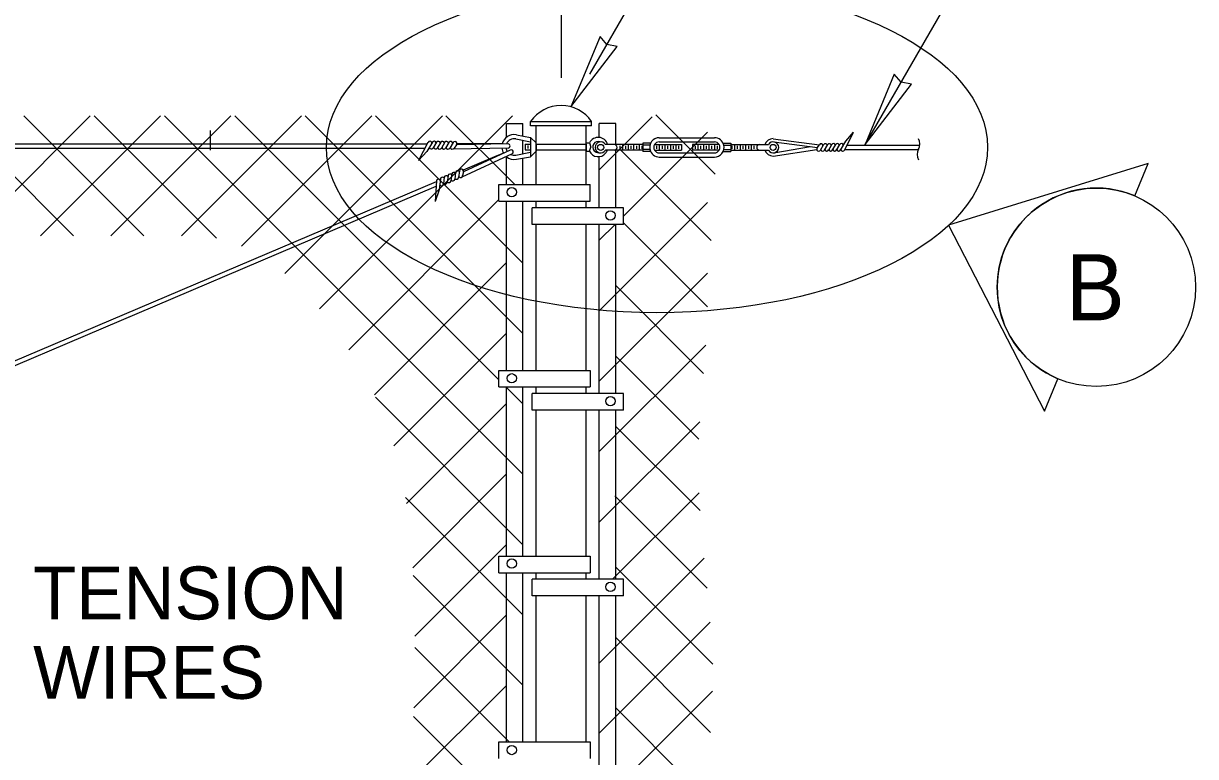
# Model space of a CAD drawing. Extents: x 99862 to 104211, y 98939 to 105076.
# Drawn here: x 102562.7 to 102917.2, y 101407.9 to 101629.6 of the extents above; entities that cross this region are included whole.
import ezdxf

# ---------------------------------------------------------------- set-up
doc = ezdxf.new("R2010")
doc.units = 0
for name, color, linetype in [('Level 11', 7, 'Continuous'), ('Level 15', 7, 'Continuous'), ('Level 2', 7, 'Continuous'), ('Level 20', 7, 'Continuous'), ('Level 4', 7, 'Continuous'), ('Level 7', 7, 'Continuous'), ('Level 9', 7, 'Continuous')]:
    doc.layers.add(name, color=color, linetype=linetype)

msp = doc.modelspace()

# ---------------------------------------------------------------- linework, layer by layer
at = {"layer": 'Level 11'}
msp.add_ellipse((102754.33, 101592.13), major_axis=(100, 0), ratio=0.5, dxfattribs=at)
at = {"layer": 'Level 15'}
for p, q in [((102725.47, 101613.16), (102725.47, 101829.45)), ((102734.02, 101614.25), (102778.38, 101691.09)), ((102817.16, 101592.77), (102846.22, 101643.09))]:
    msp.add_line(p, q, dxfattribs=at)
for points in [[(102728.32, 101604.37), (102742.32, 101622.65), (102739.2, 101623.22), (102737.15, 101625.63)], [(102728.32, 101604.37), (102742.32, 101622.65), (102739.2, 101623.22), (102737.15, 101625.63)], [(102817.27, 101592.95), (102831.27, 101611.23), (102828.15, 101611.8), (102826.1, 101614.21)], [(102817.27, 101592.95), (102831.27, 101611.23), (102828.15, 101611.8), (102826.1, 101614.21)]]:
    msp.add_lwpolyline(points, close=True, dxfattribs=at)
at = {"layer": 'Level 2'}
for p, q in [((102685.07, 101593.64), (102682.21, 101588.12)), ((102686.42, 101593.7), (102684.72, 101590.85)), ((102687.69, 101593.71), (102686.62, 101591.95)), ((102688.95, 101593.71), (102687.81, 101591.85)), ((102690.18, 101593.68), (102689.12, 101591.91)), ((102691.42, 101593.64), (102690.37, 101591.88)), ((102711.62, 101594.68), (102716.12, 101593.8)), ((102711.8, 101595.91), (102716.12, 101595.14)), ((102716.12, 101595.14), (102717.81, 101593.46)), ((102716.12, 101595.14), (102716.12, 101589.3)), ((102755.03, 101595.04), (102771.69, 101595.04)), ((102755.03, 101593.79), (102771.69, 101593.79)), ((102789.45, 101594.74), (102803.44, 101592.88)), ((102789.67, 101593.77), (102802.89, 101592.09)), ((102809.81, 101591.26), (102811.41, 101594.04)), ((102811.11, 101591.34), (102813.78, 101596.74)), ((102811.41, 101594.04), (102813.78, 101596.74)), ((102053.12, 101593.18), (102684.84, 101593.18)), ((102053.82, 101591.88), (102684.16, 101591.88)), ((102684.72, 101590.85), (102682.21, 101588.12)), ((102692.65, 101593.61), (102691.64, 101591.89)), ((102709.29, 101591.91), (102692.56, 101591.59)), ((102693.65, 101592.85), (102692.96, 101591.91)), ((102709.28, 101593.16), (102693.65, 101592.86)), ((102704.03, 101593.22), (102693.8, 101593.33)), ((102710.51, 101590.17), (102695.29, 101583.12)), ((102709.97, 101591.3), (102695.78, 101584.72)), ((102707.52, 101593.18), (102704.03, 101593.22)), ((102707.86, 101590.4), (102705.14, 101589.23)), ((102711.62, 101589.77), (102716.12, 101590.65)), ((102714.47, 101593.06), (102714.47, 101591.39)), ((102714.47, 101593.06), (102716.12, 101593.06)), ((102714.47, 101591.39), (102716.12, 101591.39)), ((102715.31, 101592.64), (102715.31, 101591.81)), ((102716.12, 101589.3), (102717.81, 101590.99)), ((102717.79, 101593.06), (102732.94, 101593.06)), ((102717.81, 101593.06), (102717.81, 101591.39)), ((102717.81, 101592.22), (102717.81, 101591.39)), ((102717.81, 101591.39), (102732.86, 101591.39)), ((102732.86, 101593.06), (102732.86, 101591.39)), ((102733.92, 101593.47), (102734.31, 101592.22)), ((102733.92, 101590.97), (102734.31, 101592.22)), ((102742.29, 101592.95), (102738.74, 101592.95)), ((102742.29, 101591.29), (102738.74, 101591.29)), ((102750.03, 101592.95), (102742.28, 101592.95)), ((102750.03, 101591.29), (102742.28, 101591.29)), ((102743.11, 101592.54), (102743.11, 101591.7)), ((102743.94, 101592.95), (102743.94, 101591.29)), ((102744.77, 101592.54), (102744.77, 101591.7)), ((102745.61, 101592.95), (102745.61, 101591.29)), ((102746.44, 101592.54), (102746.44, 101591.7)), ((102747.27, 101592.95), (102747.27, 101591.29)), ((102748.11, 101592.54), (102748.11, 101591.7)), ((102748.94, 101592.95), (102748.94, 101591.29)), ((102749.77, 101592.54), (102749.77, 101591.7)), ((102750.03, 101593.37), (102750.03, 101590.87)), ((102752.4, 101593.37), (102750.03, 101593.37)), ((102752.4, 101590.87), (102750.03, 101590.87)), ((102753.6, 101592.95), (102761.7, 101592.95)), ((102753.6, 101591.29), (102761.7, 101591.29)), ((102754.2, 101592.54), (102754.2, 101591.7)), ((102755.03, 101592.95), (102755.03, 101591.29)), ((102755.03, 101590.45), (102771.71, 101590.45)), ((102755.87, 101592.54), (102755.87, 101591.7)), ((102756.7, 101592.95), (102756.7, 101591.29)), ((102757.53, 101592.54), (102757.53, 101591.7)), ((102758.37, 101592.95), (102758.37, 101591.29)), ((102759.2, 101592.54), (102759.2, 101591.7)), ((102760.03, 101592.95), (102760.03, 101591.29)), ((102760.87, 101592.54), (102760.87, 101591.7)), ((102761.7, 101592.95), (102761.7, 101591.29)), ((102765.03, 101592.95), (102765.03, 101591.29)), ((102773.14, 101592.95), (102765.03, 101592.95)), ((102773.14, 101591.29), (102765.03, 101591.29)), ((102765.87, 101592.54), (102765.87, 101591.7)), ((102766.7, 101592.95), (102766.7, 101591.29)), ((102767.53, 101592.54), (102767.53, 101591.7)), ((102768.36, 101592.95), (102768.36, 101591.29)), ((102769.2, 101592.54), (102769.2, 101591.7)), ((102770.03, 101592.95), (102770.03, 101591.29)), ((102770.86, 101592.54), (102770.86, 101591.7)), ((102771.7, 101592.95), (102771.7, 101591.29)), ((102772.53, 101592.54), (102772.53, 101591.7)), ((102774.33, 101593.37), (102776.69, 101593.37)), ((102774.33, 101590.87), (102776.69, 101590.87)), ((102776.69, 101593.37), (102776.69, 101590.87)), ((102776.69, 101592.95), (102784.46, 101592.95)), ((102776.69, 101591.29), (102784.46, 101591.29)), ((102776.96, 101592.54), (102776.96, 101591.7)), ((102777.79, 101592.95), (102777.79, 101591.29)), ((102778.62, 101592.54), (102778.62, 101591.7)), ((102779.46, 101592.95), (102779.46, 101591.29)), ((102780.29, 101592.54), (102780.29, 101591.7)), ((102781.12, 101592.95), (102781.12, 101591.29)), ((102781.96, 101592.54), (102781.96, 101591.7)), ((102782.79, 101592.95), (102782.79, 101591.29)), ((102783.62, 101592.54), (102783.62, 101591.7)), ((102784.46, 101592.95), (102788.01, 101592.95)), ((102784.46, 101591.29), (102788.01, 101591.29)), ((102789.46, 101589.49), (102802.66, 101591.49)), ((102789.66, 101590.47), (102800.75, 101592.36)), ((102802.8, 101591.95), (102803.44, 101592.88)), ((102803.77, 101591.24), (102804.73, 101592.92)), ((102804.97, 101591.23), (102805.96, 101592.96)), ((102806.17, 101591.22), (102807.17, 101592.95)), ((102807.36, 101591.21), (102808.43, 101593.02)), ((102808.58, 101591.23), (102809.58, 101592.95)), ((102811.17, 101591.47), (102833.37, 101591.47)), ((102811.82, 101592.77), (102833.82, 101592.77)), ((102705.14, 101589.23), (102695.73, 101585.22)), ((102711.8, 101588.53), (102716.12, 101589.3)), ((102755.03, 101589.2), (102771.71, 101589.2)), ((102689.98, 101583.1), (102689.71, 101581.06)), ((102691.14, 101583.6), (102690.84, 101581.45)), ((102692.28, 101584.07), (102692.01, 101582.03)), ((102693.42, 101584.53), (102693.17, 101582.5)), ((102694.57, 101585), (102694.33, 101583.02)), ((102695.78, 101584.72), (102695.54, 101583.57)), ((102369.62, 101446.53), (102687.61, 101581.81)), ((102371.28, 101445.83), (102687.52, 101580.36)), ((102687.62, 101581.98), (102687.22, 101575.78)), ((102688.83, 101582.58), (102688.41, 101579.29)), ((102688.41, 101579.29), (102687.22, 101575.78))]:
    msp.add_line(p, q, dxfattribs=at)
for points in [[(102717.81, 101593.06), (102717.81, 101593.46)], [(102717.81, 101591.39), (102717.81, 101590.99)], [(102732.86, 101593.06), (102732.86, 101593.47), (102733.92, 101593.47)], [(102732.86, 101591.39), (102732.86, 101590.97), (102733.92, 101590.97)], [(102752.2, 101592.8), (102750.03, 101592.8)], [(102752.2, 101591.44), (102750.03, 101591.44)], [(102774.53, 101592.8), (102776.69, 101592.8)], [(102774.53, 101591.44), (102776.69, 101591.44)]]:
    msp.add_lwpolyline(points, dxfattribs=at)
for centre in [(102737.3, 101592.12), (102789.46, 101592.12)]:
    msp.add_circle(centre, 0.916, dxfattribs=at)
for centre, radius, start, end in [((102685.63, 101593.35), 0.625, 5.7789, 152.6176), ((102686.93, 101593.34), 0.625, 12.0523, 144.5017), ((102688.18, 101593.32), 0.625, 11.9735, 142.0632), ((102689.43, 101593.31), 0.625, 12.0932, 140.8462), ((102690.68, 101593.3), 0.625, 12.2252, 142.7525), ((102691.93, 101593.28), 0.625, 12.2828, 145.512), ((102693.18, 101593.27), 0.625, 318.3359, 147.4851), ((102711.14, 101592.22), 3.75, 79.8887, 166.0069), ((102711.14, 101592.22), 2.5, 78.9793, 157.7512), ((102736.56, 101592.22), 2.92, 15.3396, 154.6231), ((102736.56, 101592.22), 1.67, 69.192, 221.9482), ((102737.3, 101592.12), 1.67, 30, 330), ((102755.03, 101592.12), 2.92, 89.9981, 197.6162), ((102755.03, 101592.12), 1.67, 89.9982, 210), ((102771.69, 101592.12), 2.92, 13.5281, 90.0019), ((102771.69, 101592.12), 1.67, 329.9987, 90.0018), ((102789.46, 101592.12), 2.63, 90.0806, 160.8668), ((102789.46, 101592.12), 1.67, 210, 150), ((102830.64, 101593.14), 3.2, 330, 30), ((102686.08, 101592.28), 0.625, 194.074, 328.7383), ((102687.33, 101592.25), 0.625, 192.6758, 336.2051), ((102688.58, 101592.23), 0.625, 192.053, 328.848), ((102689.84, 101592.22), 0.625, 191.152, 331.6089), ((102691.1, 101592.21), 0.625, 192.2252, 329.3524), ((102692.41, 101592.19), 0.625, 184.6492, 332.5975), ((102711.14, 101592.22), 3.75, 185.2887, 210.187), ((102711.14, 101592.22), 2.5, 187.3793, 212.8585), ((102709.29, 101592.54), 0.625, 269.3753, 89.3753), ((102710.23, 101590.73), 0.625, 293.1269, 114.8728), ((102736.56, 101592.22), 2.92, 205.3769, 319.9883), ((102736.56, 101592.22), 1.67, 221.9482, 275.0474), ((102736.56, 101592.22), 2.92, 319.9883, 341.2905), ((102741.44, 101592.12), 0.833, 270, 90), ((102755.03, 101592.12), 2.92, 193.5247, 270), ((102755.03, 101592.12), 1.67, 210, 270), ((102771.69, 101592.12), 2.92, 270, 13.5281), ((102771.69, 101592.12), 1.67, 270, 329.9987), ((102785.31, 101592.12), 0.833, 90, 270), ((102789.46, 101592.12), 2.63, 197.8761, 270.0806), ((102803.26, 101591.56), 0.605, 139.3585, 332.2423), ((102803.99, 101592.62), 0.605, 5.6718, 153.6201), ((102804.47, 101591.57), 0.605, 193.3054, 333.9105), ((102805.26, 101592.62), 0.605, 13.2478, 150.375), ((102805.68, 101591.58), 0.605, 193.2478, 335.9662), ((102806.47, 101592.63), 0.605, 12.1746, 152.6315), ((102806.89, 101591.59), 0.605, 193.1158, 337.2277), ((102807.69, 101592.64), 0.605, 13.0756, 149.8707), ((102808.1, 101591.59), 0.605, 192.9962, 336.4359), ((102808.9, 101592.65), 0.605, 13.6984, 157.2277), ((102809.31, 101591.6), 0.605, 193.075, 334.6977), ((102810.11, 101592.65), 0.605, 15.0966, 149.7609), ((102810.57, 101591.61), 0.605, 186.8015, 333.6402), ((102836.18, 101589.95), 3.2, 150, 210), ((102711.14, 101592.22), 3.75, 230.0889, 280.1113), ((102711.14, 101592.22), 2.5, 244.5938, 281.1362), ((102689.44, 101582.45), 0.625, 35.8039, 168.2533), ((102690.59, 101582.94), 0.625, 35.7251, 165.8148), ((102691.74, 101583.44), 0.625, 35.8448, 164.5978), ((102692.89, 101583.93), 0.625, 35.9768, 166.5041), ((102693.71, 101583.1), 0.625, 215.9768, 353.104), ((102694.04, 101584.42), 0.625, 36.0344, 169.2636), ((102694.92, 101583.61), 0.625, 208.4008, 356.3491), ((102695.19, 101584.91), 0.625, 342.0875, 174.9712), ((102688.24, 101581.94), 0.625, 29.5305, 176.3692), ((102689.09, 101581.14), 0.625, 217.8256, 352.4899), ((102690.24, 101581.62), 0.625, 216.4274, 359.9567), ((102691.39, 101582.11), 0.625, 215.8046, 352.5996), ((102692.56, 101582.6), 0.625, 214.9036, 355.3605)]:
    msp.add_arc(centre, radius, start, end, dxfattribs=at)
at = {"layer": 'Level 4'}
for p, q in [((102577.89, 101565.38), (102541.59, 101601.68)), ((102546.63, 101565.38), (102582.93, 101601.68)), ((102599.15, 101565.38), (102562.86, 101601.68)), ((102567.91, 101565.38), (102604.21, 101601.68)), ((102621.13, 101564.66), (102584.12, 101601.68)), ((102589.16, 101565.38), (102625.47, 101601.68)), ((102713.8, 101493.25), (102605.37, 101601.68)), ((102610.5, 101565.38), (102646.8, 101601.68)), ((102706.53, 101521.79), (102626.64, 101601.68)), ((102628.71, 101562.27), (102668.13, 101601.68)), ((102641.76, 101554.01), (102689.44, 101601.68)), ((102713.8, 101535.8), (102647.92, 101601.68)), ((102652.25, 101543.29), (102710.65, 101601.68)), ((102713.8, 101557.08), (102669.21, 101601.68)), ((102711.29, 101580.86), (102690.48, 101601.68)), ((102736.87, 101585.33), (102752.91, 101601.36)), ((102771.96, 101584.05), (102754.01, 101602)), ((102619.28, 101591.26), (102619.28, 101597.25)), ((102744.15, 101571.29), (102769.61, 101596.75)), ((102770.76, 101563.97), (102743.44, 101591.29)), ((102661.16, 101530.94), (102706.53, 101576.31)), ((102736.87, 101542.72), (102769.61, 101575.44)), ((102736.87, 101564.02), (102741.69, 101568.83)), ((102769.59, 101543.85), (102744.15, 101569.29)), ((102668.84, 101517.3), (102708.8, 101557.26)), ((102736.87, 101521.39), (102769.61, 101554.12)), ((102768.39, 101523.77), (102741.96, 101550.2)), ((102674.74, 101501.89), (102708.77, 101535.92)), ((102736.87, 101500.1), (102769.06, 101532.28)), ((102766.96, 101503.92), (102741.82, 101529.06)), ((102713.8, 101514.52), (102708.65, 101519.67)), ((102713.8, 101471.96), (102669.16, 101516.62)), ((102678.55, 101484.41), (102708.8, 101514.65)), ((102736.87, 101478.79), (102767.24, 101509.15)), ((102767.35, 101482.26), (102741.87, 101507.73)), ((102680.45, 101464.96), (102708.76, 101493.27)), ((102740.86, 101461.5), (102767.04, 101487.68)), ((102713.8, 101450.71), (102678.26, 101486.26)), ((102769.46, 101458.86), (102741.57, 101486.75)), ((102681.1, 101444.32), (102708.77, 101471.99)), ((102736.87, 101436.19), (102768.57, 101467.89)), ((102713.8, 101429.46), (102680.58, 101462.69)), ((102771.18, 101435.87), (102741.86, 101465.19)), ((102680.75, 101422.67), (102708.75, 101450.67)), ((102736.87, 101414.95), (102770.41, 101448.49)), ((102770.55, 101415.2), (102741.84, 101443.91)), ((102709.63, 101412.34), (102681.11, 101440.87)), ((102679.62, 101400.26), (102708.77, 101429.41)), ((102736.87, 101393.5), (102771.1, 101427.7)), ((102713.8, 101386.9), (102680.65, 101420.06)), ((102768.22, 101396.28), (102741.86, 101422.65))]:
    msp.add_line(p, q, dxfattribs=at)
at = {"layer": 'Level 7'}
for p, q in [((102708.78, 101599.3), (102713.8, 101599.3)), ((102708.78, 101595.14), (102708.78, 101599.3)), ((102713.8, 101595.56), (102713.8, 101599.3)), ((102716.11, 101599.92), (102734.56, 101599.92)), ((102716.11, 101598.67), (102716.11, 101599.92)), ((102734.56, 101598.67), (102716.11, 101598.67)), ((102717.82, 101580.86), (102717.82, 101598.67)), ((102732.86, 101580.86), (102732.86, 101598.67)), ((102734.56, 101598.67), (102734.56, 101599.92)), ((102736.87, 101595.12), (102736.87, 101599.3)), ((102741.89, 101599.3), (102736.87, 101599.3)), ((102741.89, 101592.95), (102741.89, 101599.3)), ((102713.8, 101591.31), (102713.8, 101594.25)), ((102713.8, 101590.2), (102713.8, 101591.31)), ((102741.89, 101590.02), (102741.89, 101591.29)), ((102708.78, 101580.86), (102708.78, 101589.31)), ((102713.8, 101580.86), (102713.8, 101588.89)), ((102736.87, 101573.84), (102736.87, 101589.32)), ((102741.89, 101573.84), (102741.89, 101590.02)), ((102706.53, 101580.86), (102734.12, 101580.86)), ((102706.53, 101575.85), (102706.53, 101580.86)), ((102734.12, 101575.85), (102734.12, 101580.86)), ((102706.53, 101575.85), (102734.12, 101575.85)), ((102708.78, 101524.69), (102708.78, 101575.85)), ((102713.8, 101524.69), (102713.8, 101575.85)), ((102744.15, 101573.84), (102716.56, 101573.84)), ((102716.56, 101568.83), (102716.56, 101573.84)), ((102717.82, 101573.84), (102717.82, 101575.85)), ((102732.86, 101573.84), (102732.86, 101575.85)), ((102744.15, 101568.83), (102744.15, 101573.84)), ((102744.15, 101568.83), (102716.56, 101568.83)), ((102717.82, 101524.69), (102717.82, 101568.83)), ((102732.86, 101524.69), (102732.86, 101568.83)), ((102736.87, 101517.67), (102736.87, 101568.83)), ((102741.89, 101517.67), (102741.89, 101568.83)), ((102706.53, 101524.69), (102734.12, 101524.69)), ((102706.53, 101519.67), (102706.53, 101524.69)), ((102734.12, 101524.69), (102734.12, 101519.67)), ((102706.53, 101519.67), (102734.12, 101519.67)), ((102708.78, 101468.52), (102708.78, 101519.67)), ((102713.8, 101468.52), (102713.8, 101519.67)), ((102717.82, 101517.67), (102717.82, 101519.67)), ((102732.86, 101517.67), (102732.86, 101519.67)), ((102744.15, 101517.67), (102716.56, 101517.67)), ((102716.56, 101512.66), (102716.56, 101517.67)), ((102744.15, 101512.66), (102744.15, 101517.67)), ((102744.15, 101512.66), (102716.56, 101512.66)), ((102717.82, 101468.52), (102717.82, 101512.66)), ((102732.86, 101468.52), (102732.86, 101512.66)), ((102736.87, 101461.5), (102736.87, 101512.66)), ((102741.89, 101461.5), (102741.89, 101512.66)), ((102706.53, 101463.5), (102706.53, 101468.52)), ((102706.53, 101468.52), (102726.48, 101468.52)), ((102726.48, 101468.52), (102734.12, 101468.52)), ((102734.12, 101468.52), (102734.12, 101463.5)), ((102706.53, 101463.5), (102734.12, 101463.5)), ((102708.78, 101412.34), (102708.78, 101463.5)), ((102713.8, 101412.34), (102713.8, 101463.5)), ((102717.82, 101461.5), (102717.82, 101463.5)), ((102732.86, 101461.5), (102732.86, 101463.5)), ((102744.15, 101461.5), (102716.56, 101461.5)), ((102716.56, 101456.48), (102716.56, 101461.5)), ((102744.15, 101456.48), (102744.15, 101461.5)), ((102744.15, 101456.48), (102716.56, 101456.48)), ((102717.82, 101429.14), (102717.82, 101456.48)), ((102732.86, 101429.14), (102732.86, 101456.48)), ((102736.87, 101405.32), (102736.87, 101456.48)), ((102741.89, 101405.32), (102741.89, 101456.48)), ((102717.82, 101412.34), (102717.82, 101429.14)), ((102732.86, 101412.34), (102732.86, 101429.14)), ((102706.53, 101412.34), (102734.12, 101412.34)), ((102706.53, 101407.33), (102706.53, 101412.34)), ((102734.12, 101412.34), (102734.12, 101407.33))]:
    msp.add_line(p, q, dxfattribs=at)
for centre in [(102710.42, 101578.57), (102740.25, 101571.55), (102710.42, 101522.28), (102740.25, 101515.37), (102710.42, 101466.26), (102740.25, 101459.2), (102710.42, 101409.88)]:
    msp.add_circle(centre, 1.41, dxfattribs=at)
msp.add_arc((102725.34, 101593.58), 11.2, 34.5285, 145.4715, dxfattribs=at)
at = {"layer": 'Level 9'}
for p, q in [((102902.93, 101587.25), (102842.53, 101568.57)), ((102898.83, 101577.48), (102902.93, 101587.25)), ((102842.53, 101568.57), (102871.51, 101512.38)), ((102871.51, 101512.38), (102875.61, 101522.15))]:
    msp.add_line(p, q, dxfattribs=at)
msp.add_circle((102887.22, 101549.81), 30, dxfattribs=at)
msp.add_arc((102887.22, 101549.81), 30, 67.23, 247.2344, dxfattribs=at)

# ---------------------------------------------------------------- texts
at = {"layer": 'Level 20'}
msp.add_text('B', height=20, dxfattribs=at).set_placement((102877.97, 101539.81))
for s, p in [('TENSION', (102565.64, 101449.36)), ('WIRES', (102565.64, 101425.36))]:
    msp.add_text(s, height=16, rotation=360, dxfattribs=at).set_placement(p)

doc.saveas('drawing.dxf')
